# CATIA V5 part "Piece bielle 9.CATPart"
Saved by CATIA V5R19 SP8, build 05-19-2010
Part number: Piece bielle 9
Bounding box of the stored display mesh (mm): x -47.985 to 37.738, y -108 to 40.809, z 3.091 to 14.909
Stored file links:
  G:\EU_thinkMotion\CFAO_2010\MMS_groupe3\MMS_groupe3\A reprendre\lpastor\lpastor\Piece bielle 9.CATPart
  C:\Users\Loïc\Documents\IFMA\Cours 2A\CFAO\Thinkmotion\Fourche avant.CATProduct
  G:\EU_thinkMotion\CFAO_2010\MMS_groupe3\MMS_groupe3\A reprendre\lpastor\lpastor\Squelette bielle 9.CATPart
  G:\EU_thinkMotion\CFAO_2010\MMS_groupe3\MMS_groupe3\A reprendre\lpastor\lpastor\Pieces.CATProduct
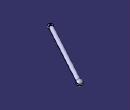
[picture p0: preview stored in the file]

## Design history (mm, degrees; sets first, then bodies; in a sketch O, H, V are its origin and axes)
External parameters (linked from other documents)
  External.Parametre_rayon_interieur_rotule_haute = 0.003
  External.Parametre_rayon_exterieur_rotule_haute = 0.006
  External.Parametre_rayon_bielle_9 = 0.004
  External.Parametre_rayon_exterieur_rotule_basse = 0.005
  External.Parametre_rayon_interieur_rotule_basse = 0.003
Set1
  Plane1: linked copy from another document
  Line1 "Droite EF (Bielle 9)": linked copy from another document
  Plane2: linked copy from another document
  Point1: linked copy from another document
  Plane3: linked copy from another document
  Line2 "Droite E (bielle 9)": linked copy from another document
  Plane4: linked copy from another document
  Line3 "Droite F (bielle 9)": linked copy from another document
Body1 (main body)
  Sketch1 on Plane1, origin (-51.1091, -94.0403, 0), H (0.8786, -0.4775, 0), V (0, 0, 1)
    circle A1 centre (11.4032, 9) radius 4
    point P1 (11.4032, 9)
    reference projected point E1 (11.4032, 9) from Point1
    radius A1 = 4 {= External.Parametre_rayon_bielle_9}
    coincidence: P1 E1
  Pad1: profile Sketch1, direction (-0.4775, -0.8786, 0), up to Plane2
  Sketch2 on Plane3, origin (0, 0, 9), H (1, 0, 0), V (0, 1, 0)
    arc A1 centre (32, 35) radius 6 from (29.1349, 29.7283) to (34.8651, 40.2717) ccw
    arc A2 centre (32, 35) radius 3 from (30.5675, 32.3641) to (33.4325, 37.6359) ccw
    point P2 (32, 35)
    reference projected point E1 (32, 35) from Line2
    line L1 (34.8651, 40.2717) -> (33.4325, 37.6359)
    reference projected line E2 (32, 35) -> (-43, -103) from Line1
    reference projected line E3 (32, 35) -> (-43, -103) from Line1
    point P4 (29.1349, 29.7283)
    point P6 (30.5675, 32.3641)
    line L2 (30.5675, 32.3641) -> (29.1349, 29.7283)
    radius A1 = 6 {= External.Parametre_rayon_exterieur_rotule_haute}
    radius A2 = 3 {= External.Parametre_rayon_interieur_rotule_haute}
    concentricity: A2 A1
    coincidence: P2 E1, L1 E3, L1 P4, L1 P6, L1 L2
    parallelism: L1 E2
  Shaft1: profile Sketch2, axis Sketch2.L1, angle 360
  Sketch3 on Plane2, origin (20.0523, 36.9407, 0), H (0.8786, -0.4775, 0), V (0, 0, 1)
    line L1 (1.4242, 10.5) -> (21.4242, 10.5)
    line L2 (21.4242, 10.5) -> (21.4242, 7.5)
    line L3 (21.4242, 7.5) -> (1.4242, 7.5)
    line L4 (1.4242, 7.5) -> (1.4242, 10.5)
    reference projected line E1 (11.4242, -50) -> (11.4242, 50) from Line2
    reference projected line E2 (11.4242, -50) -> (11.4242, 50) from Line2
    reference intersected line E3 through (0, 9) direction (-1, 0) from Plane3
    reference intersected line E4 through (0, 9) direction (-1, 0) from Plane3
    distance E1 L2 = 10
    distance E2 L4 = 10
    distance E3 L1 = 1.5
    distance E4 L3 = 1.5
    horizontal: L1 H, L3 H
    vertical: L2 V, L4 V
  Pocket1: profile Sketch3, direction (0.4775, 0.8786, 0), through (limit type 3)
  Sketch4 on Plane4, origin (0, 0, 9), H (1, 0, 0), V (0, 1, 0)
    arc A1 centre (-43, -103) radius 5 from (-45.3876, -107.3931) to (-40.6124, -98.6069) ccw
    arc A2 centre (-43, -103) radius 3 from (-44.4325, -105.6359) to (-41.5675, -100.3641) ccw
    point P2 (-43, -103)
    reference projected point E1 (-43, -103) from Line3
    line L1 (-45.3876, -107.3931) -> (-44.4325, -105.6359)
    reference projected line E2 (32, 35) -> (-43, -103) from Line1
    reference projected line E3 (32, 35) -> (-43, -103) from Line1
    point P3 (-40.6124, -98.6069)
    point P5 (-41.5675, -100.3641)
    line L2 (-41.5675, -100.3641) -> (-40.6124, -98.6069)
    radius A2 = 3 {= External.Parametre_rayon_interieur_rotule_basse}
    radius A1 = 5 {= External.Parametre_rayon_exterieur_rotule_basse}
    concentricity: A2 A1
    coincidence: P2 E1, L1 E3, L1 P3, L1 P5, L1 L2
    parallelism: L1 E2
  Shaft2: profile Sketch4, axis Sketch4.L1, angle 360
  Sketch5 on Plane1, origin (-51.1091, -94.0403, 0), H (0.8786, -0.4775, 0), V (0, 0, 1)
    line L1 (1.4032, 11) -> (21.4032, 11)
    line L2 (21.4032, 11) -> (21.4032, 7)
    line L3 (21.4032, 7) -> (1.4032, 7)
    line L4 (1.4032, 7) -> (1.4032, 11)
    reference projected line E1 (11.4032, -50) -> (11.4032, 50) from Line3
    reference projected line E2 (11.4032, -50) -> (11.4032, 50) from Line3
    reference intersected line E3 through (0, 9) direction (-1, 0) from Plane4
    reference intersected line E4 through (0, 9) direction (-1, 0) from Plane4
    distance E1 L2 = 10
    distance E2 L4 = 10
    distance E3 L1 = 2
    distance E4 L3 = 2
    horizontal: L1 H, L3 H
    vertical: L2 V, L4 V
  Pocket2: profile Sketch5, direction (-0.4775, -0.8786, 0), through (limit type 3), outer side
